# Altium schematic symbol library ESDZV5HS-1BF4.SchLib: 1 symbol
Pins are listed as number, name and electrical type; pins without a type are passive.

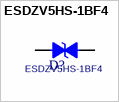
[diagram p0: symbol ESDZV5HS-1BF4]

## ESDZV5HS-1BF4
designator D?
footprint ST_0201B_CSP_ap
pins: 1, 2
